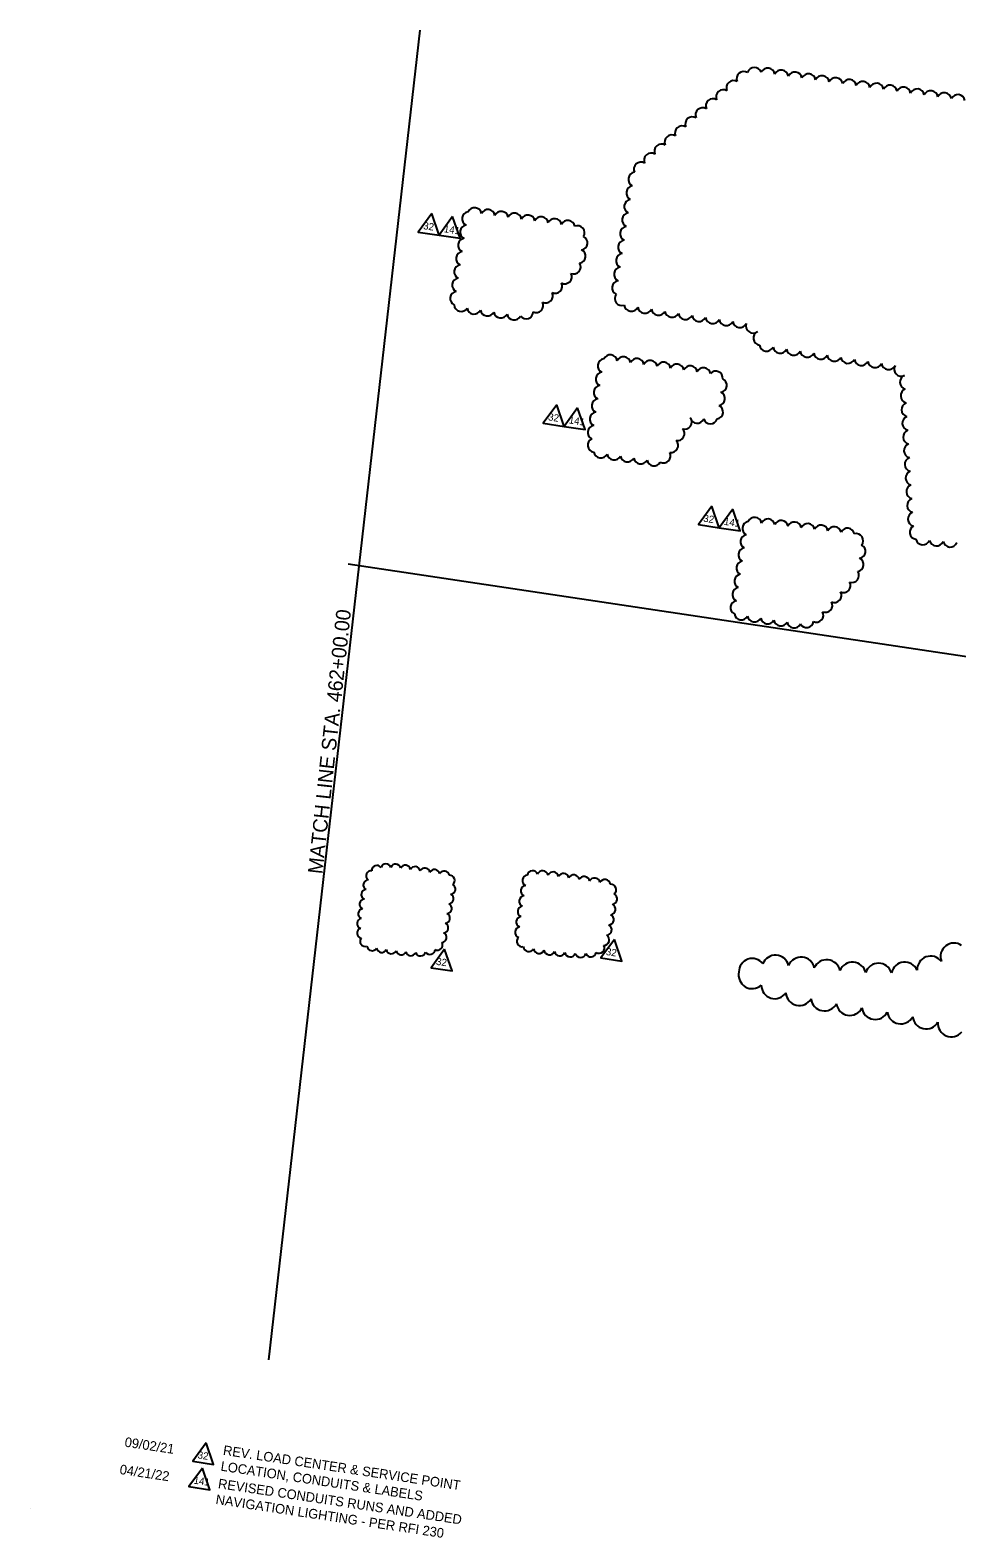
# Model space of a CAD drawing. Extents: x 924436 to 925782, y 636346 to 637319.
# Drawn here: x 924436 to 924943, y 636495 to 637319 of the extents above; entities that cross this region are included whole.
import ezdxf

# ---------------------------------------------------------------- set-up
doc = ezdxf.new("R2010")
doc.units = 0
for name, color, linetype in [('ActivePointCell_dp', 7, 'Continuous'), ('AdhocPoint_dp', 7, 'Continuous'), ('Cloud_dp', 7, 'Continuous'), ('MatchLines_dp', 7, 'Continuous'), ('TextLabel', 7, 'Continuous'), ('TextNotes', 7, 'Continuous')]:
    doc.layers.add(name, color=color, linetype=linetype)

msp = doc.modelspace()

# ---------------------------------------------------------------- linework, layer by layer
at = {"layer": 'ActivePointCell_dp'}
msp.add_line((924609.88, 637027.58), (925702.36, 636864), dxfattribs=at)
at = {"layer": 'AdhocPoint_dp'}
msp.add_line((924435.98, 636511.22), (924435.98, 636511.22), dxfattribs=at)
at = {"layer": 'Cloud_dp'}
for points in [[(924655.53, 637219.18), (924648.17, 637209.03), (924659.6, 637207.32)], [(924666.96, 637217.47), (924659.6, 637207.32), (924671.02, 637205.61)], [(924723.84, 637114.64), (924716.48, 637104.49), (924727.91, 637102.78)], [(924735.27, 637112.93), (924727.91, 637102.78), (924739.33, 637101.07)], [(924808.68, 637059.19), (924801.32, 637049.04), (924812.75, 637047.33)], [(924820.11, 637057.48), (924812.75, 637047.33), (924824.17, 637045.62)], [(924755.42, 636822.21), (924748.06, 636812.07), (924759.49, 636810.36)], [(924662.57, 636816.88), (924655.21, 636806.73), (924666.63, 636805.02)]]:
    msp.add_lwpolyline(points, close=True, dxfattribs=at)
for centre, radius, start, end in [((924826.13, 637292.91), 3.93, 58.88945, 203.88945), ((924831.93, 637295.16), 3.93, 18.56609, 163.56609), ((924839.2, 637294.72), 3.93, 9.6019, 154.6019), ((924846.63, 637293.69), 3.93, 9.6019, 154.6019), ((924854.06, 637292.66), 3.93, 9.6019, 154.6019), ((924861.48, 637291.63), 3.93, 9.6019, 154.6019), ((924820.51, 637287.95), 3.93, 58.88945, 203.88945), ((924868.91, 637290.6), 3.93, 9.6019, 154.6019), ((924876.33, 637289.57), 3.93, 9.6019, 154.6019), ((924883.76, 637288.54), 3.93, 9.6019, 154.6019), ((924891.18, 637287.51), 3.93, 9.6019, 154.6019), ((924898.61, 637286.48), 3.93, 9.6019, 154.6019), ((924906.03, 637285.45), 3.93, 9.6019, 154.6019), ((924913.46, 637284.42), 3.93, 9.6019, 154.6019), ((924920.88, 637283.39), 3.93, 9.6019, 154.6019), ((924809.26, 637278.04), 3.93, 58.88945, 203.88945), ((924814.88, 637282.99), 3.93, 58.88945, 203.88945), ((924928.31, 637282.36), 3.93, 9.6019, 154.6019), ((924935.73, 637281.33), 3.93, 9.6019, 154.6019), ((924943.16, 637280.28), 3.94, 9.27297, 154.27297), ((924798.01, 637268.12), 3.93, 58.88945, 203.88945), ((924803.63, 637273.08), 3.93, 58.88945, 203.88945), ((924792.39, 637263.17), 3.93, 58.88945, 203.88945), ((924781.14, 637253.25), 3.93, 58.88945, 203.88945), ((924786.76, 637258.21), 3.93, 58.88945, 203.88945), ((924769.89, 637243.34), 3.93, 58.88945, 203.88945), ((924775.51, 637248.3), 3.93, 58.88945, 203.88945), ((924766.91, 637237.87), 3.93, 98.98411, 243.98411), ((924765.8, 637230.45), 3.93, 98.98411, 243.98411), ((924678.9, 637218.52), 3.86, 9.69938, 154.69938), ((924686.19, 637217.52), 3.86, 9.69938, 154.69938), ((924764.69, 637223.04), 3.93, 98.98411, 243.98411), ((924674.93, 637209.08), 3.86, 98.98411, 243.98411), ((924676.02, 637216.36), 3.86, 98.98411, 243.98411), ((924693.47, 637216.52), 3.86, 9.69938, 154.69938), ((924700.76, 637215.52), 3.86, 9.69938, 154.69938), ((924708.05, 637214.52), 3.86, 9.69938, 154.69938), ((924715.33, 637213.52), 3.86, 9.69938, 154.69938), ((924722.62, 637212.53), 3.86, 9.69938, 154.69938), ((924729.9, 637211.53), 3.86, 9.69938, 154.69938), ((924763.58, 637215.63), 3.93, 98.98411, 243.98411), ((924673.84, 637201.81), 3.86, 98.98411, 243.98411), ((924735.21, 637208.63), 3.86, 328.02413, 113.02413), ((924736.81, 637203.11), 3.86, 279.30403, 64.30403), ((924761.36, 637200.8), 3.93, 98.98411, 243.98411), ((924762.47, 637208.21), 3.93, 98.98411, 243.98411), ((924672.75, 637194.54), 3.86, 98.98411, 243.98411), ((924735.76, 637195.83), 3.86, 279.30403, 64.30403), ((924760.25, 637193.39), 3.93, 98.98411, 243.98411), ((924671.66, 637187.26), 3.86, 98.98411, 243.98411), ((924733.13, 637189.98), 3.86, 247.21121, 32.21121), ((924759.14, 637185.97), 3.93, 98.98411, 243.98411), ((924670.57, 637179.99), 3.86, 98.98411, 243.98411), ((924723.05, 637179.39), 3.86, 242.81513, 27.81513), ((924728.22, 637184.62), 3.86, 242.81513, 27.81513), ((924758.03, 637178.56), 3.93, 98.98411, 243.98411), ((924669.48, 637172.72), 3.86, 98.98411, 243.98411), ((924717.88, 637174.16), 3.86, 242.81513, 27.81513), ((924759.49, 637172.72), 3.93, 144.02662, 289.02662), ((924671.64, 637169.46), 3.85, 183.16682, 328.16682), ((924678.72, 637168.03), 3.86, 188.98411, 333.98411), ((924685.99, 637166.95), 3.86, 188.98411, 333.98411), ((924693.27, 637165.86), 3.86, 188.98411, 333.98411), ((924700.54, 637164.77), 3.86, 188.98411, 333.98411), ((924707.09, 637165.38), 3.85, 216.78941, 1.78941), ((924712.71, 637168.93), 3.86, 242.81513, 27.81513), ((924764.65, 637169.62), 3.93, 188.98411, 333.98411), ((924772.06, 637168.51), 3.93, 188.98411, 333.98411), ((924779.48, 637167.4), 3.93, 188.98411, 333.98411), ((924786.89, 637166.29), 3.93, 188.98411, 333.98411), ((924794.3, 637165.18), 3.93, 188.98411, 333.98411), ((924801.72, 637164.07), 3.93, 188.98411, 333.98411), ((924809.13, 637162.96), 3.93, 188.98411, 333.98411), ((924816.55, 637161.85), 3.93, 188.98411, 333.98411), ((924823.96, 637160.74), 3.93, 188.98411, 333.98411), ((924831.21, 637157.75), 3.93, 161.22808, 306.22808), ((924835.28, 637151.1), 3.89, 116.6552, 261.6552), ((924838.59, 637147.86), 3.93, 188.89284, 333.89284), ((924750.17, 637135.85), 3.86, 98.98411, 243.98411), ((924753.05, 637138.01), 3.86, 9.68197, 154.68197), ((924760.34, 637137.01), 3.86, 9.68197, 154.68197), ((924767.64, 637136.01), 3.86, 9.68197, 154.68197), ((924774.93, 637135.01), 3.86, 9.68197, 154.68197), ((924846.01, 637146.74), 3.93, 188.89284, 333.89284), ((924853.42, 637145.62), 3.93, 188.89284, 333.89284), ((924860.83, 637144.49), 3.93, 188.89284, 333.89284), ((924868.24, 637143.37), 3.93, 188.89284, 333.89284), ((924875.65, 637142.25), 3.93, 188.89284, 333.89284), ((924883.06, 637141.13), 3.93, 188.89284, 333.89284), ((924890.48, 637140.01), 3.93, 188.89284, 333.89284), ((924749.08, 637128.57), 3.86, 98.98411, 243.98411), ((924782.22, 637134.01), 3.86, 9.68197, 154.68197), ((924789.51, 637133), 3.86, 9.68197, 154.68197), ((924796.8, 637132), 3.86, 9.68197, 154.68197), ((924804.09, 637131), 3.86, 9.68197, 154.68197), ((924810.8, 637129.12), 3.86, 353.97234, 138.97234), ((924897.89, 637138.88), 3.93, 188.89284, 333.89284), ((924905.31, 637137.76), 3.94, 188.89284, 333.89284), ((924912.27, 637134.12), 3.92, 150.88593, 295.88593), ((924915.38, 637126.93), 3.93, 110.89209, 255.89209), ((924747.99, 637121.29), 3.86, 98.98411, 243.98411), ((924812.98, 637125.23), 3.86, 279.5168, 64.5168), ((924915.82, 637119.44), 3.93, 110.89209, 255.89209), ((924746.9, 637114.02), 3.86, 98.98411, 243.98411), ((924810.94, 637110.66), 3.86, 279.5168, 64.5168), ((924811.96, 637117.94), 3.86, 279.5168, 64.5168), ((924916.27, 637111.96), 3.93, 110.89209, 255.89209), ((924745.81, 637106.74), 3.86, 98.98411, 243.98411), ((924793.79, 637105.16), 3.86, 251.64788, 36.64788), ((924800.65, 637108.31), 3.86, 192.74467, 337.74467), ((924807.9, 637108.01), 3.86, 197.49791, 342.49791), ((924916.71, 637104.48), 3.93, 110.89209, 255.89209), ((924744.72, 637099.46), 3.86, 98.98411, 243.98411), ((924789.83, 637098.79), 3.86, 259.51444, 44.51444), ((924917.15, 637096.99), 3.93, 110.89209, 255.89209), ((924744.72, 637092.52), 3.86, 115.97008, 260.97008), ((924786.38, 637092.29), 3.86, 259.51444, 44.51444), ((924917.6, 637089.51), 3.93, 110.89209, 255.89209), ((924747.92, 637089.32), 3.86, 188.98411, 333.98411), ((924755.2, 637088.23), 3.86, 188.98411, 333.98411), ((924762.48, 637087.14), 3.86, 188.98411, 333.98411), ((924769.76, 637086.05), 3.86, 188.98411, 333.98411), ((924777.03, 637084.96), 3.86, 188.98411, 333.98411), ((924782.26, 637086.7), 3.86, 242.8424, 27.8424), ((924918.04, 637082.03), 3.93, 110.89209, 255.89209), ((924918.49, 637074.54), 3.93, 110.89209, 255.89209), ((924918.93, 637067.06), 3.93, 110.89209, 255.89209), ((924919.37, 637059.58), 3.93, 110.89209, 255.89209), ((924829.14, 637046.98), 3.83, 98.98411, 243.98411), ((924832.03, 637049.2), 3.83, 10.84278, 155.84278), ((924839.28, 637048.35), 3.83, 10.84278, 155.84278), ((924846.54, 637047.5), 3.83, 10.84278, 155.84278), ((924853.79, 637046.66), 3.83, 10.84278, 155.84278), ((924861.05, 637045.81), 3.83, 10.84278, 155.84278), ((924868.3, 637044.96), 3.83, 10.84278, 155.84278), ((924875.55, 637044.12), 3.83, 10.84278, 155.84278), ((924919.82, 637052.09), 3.94, 110.89209, 255.89209), ((924920.66, 637044.87), 3.85, 117.95353, 262.95353), ((924828.05, 637039.76), 3.83, 98.98411, 243.98411), ((924882.81, 637043.27), 3.83, 10.84278, 155.84278), ((924887.56, 637040.29), 3.83, 320.05109, 105.05109), ((924924.02, 637041.92), 3.93, 192.80022, 337.80022), ((924931.49, 637041.31), 3.93, 192.80022, 337.80022), ((924938.97, 637040.69), 3.93, 192.80022, 337.80022), ((924826.97, 637032.54), 3.83, 98.98411, 243.98411), ((924888.84, 637034.39), 3.83, 279.29199, 64.29199), ((924825.89, 637025.31), 3.83, 98.98411, 243.98411), ((924885.27, 637021.19), 3.83, 249.85694, 34.85694), ((924887.79, 637027.16), 3.83, 279.29199, 64.29199), ((924824.81, 637018.09), 3.83, 98.98411, 243.98411), ((924880.64, 637015.68), 3.83, 245.07106, 30.07106), ((924822.65, 637003.65), 3.83, 98.98411, 243.98411), ((924823.73, 637010.87), 3.83, 98.98411, 243.98411), ((924870.78, 637004.9), 3.83, 245.07106, 30.07106), ((924875.71, 637010.29), 3.83, 245.07106, 30.07106), ((924824.75, 637000.76), 3.83, 188.30813, 333.30813), ((924831.95, 636999.64), 3.83, 188.98411, 333.98411), ((924865.86, 636999.51), 3.83, 245.07106, 30.07106), ((924839.18, 636998.56), 3.83, 188.98411, 333.98411), ((924846.4, 636997.47), 3.83, 188.98411, 333.98411), ((924853.62, 636996.39), 3.83, 188.98411, 333.98411), ((924860.44, 636996.51), 3.83, 207.92147, 352.92147), ((924622.48, 636856.98), 2.82, 85.72902, 230.72902), ((924625.52, 636859.86), 2.82, 36.48479, 181.48479), ((924630.49, 636860.73), 2.82, 18.22494, 163.22494), ((924635.78, 636860.54), 2.82, 12.74786, 157.74786), ((924641.09, 636859.97), 2.82, 9.88809, 154.88809), ((924646.4, 636859.21), 2.82, 8.98411, 153.98411), ((924651.72, 636858.42), 2.82, 8.98411, 153.98411), ((924657.05, 636857.62), 2.82, 8.98411, 153.98411), ((924662.37, 636856.82), 2.82, 8.98411, 153.98411), ((924710.6, 636856.75), 3.01, 22.10621, 167.10621), ((924716.16, 636856.72), 3.01, 12.25515, 157.25515), ((924721.83, 636856.1), 3.01, 10.2339, 155.2339), ((924727.51, 636855.32), 3.01, 9.21064, 154.21064), ((924620.92, 636851.98), 2.82, 94.43828, 239.43828), ((924665.28, 636854.44), 2.82, 307.56851, 92.56851), ((924665.67, 636849.72), 2.82, 276.72488, 61.72488), ((924707.21, 636848.79), 3.01, 98.98411, 243.98411), ((924708.09, 636854.44), 3.01, 98.21119, 243.21119), ((924733.18, 636854.48), 3.01, 8.98411, 153.98411), ((924738.86, 636853.63), 3.01, 8.98411, 153.98411), ((924744.53, 636852.78), 3.01, 8.98411, 153.98411), ((924750.21, 636851.93), 3.01, 8.98411, 153.98411), ((924753.39, 636849.4), 3.01, 308.91031, 93.91031), ((924618.9, 636841.47), 2.82, 98.30208, 243.30208), ((924619.82, 636846.75), 2.82, 96.94529, 241.94529), ((924664.66, 636844.43), 2.82, 276.75589, 61.75589), ((924706.36, 636843.11), 3.01, 98.98411, 243.98411), ((924753.92, 636844.37), 3.01, 278.18047, 63.18047), ((924617.56, 636830.87), 2.82, 103.36672, 248.36672), ((924618.11, 636836.17), 2.82, 99.77206, 244.77206), ((924662.71, 636833.84), 2.82, 277.48651, 62.48651), ((924663.67, 636839.14), 2.82, 277.05268, 62.05268), ((924704.72, 636831.76), 3.01, 100.03156, 245.03156), ((924705.51, 636837.44), 3.01, 99.13208, 244.13208), ((924752.03, 636833.06), 3.01, 277.48854, 62.48854), ((924752.99, 636838.71), 3.01, 278.18042, 63.18042), ((924617.54, 636825.61), 2.82, 111.02904, 256.02904), ((924660.84, 636823.25), 2.82, 276.32619, 61.32619), ((924661.8, 636828.52), 2.82, 278.0572, 63.0572), ((924704.08, 636826.09), 3.01, 102.07512, 247.07512), ((924750.94, 636827.46), 3.01, 275.51216, 60.51216), ((924619.15, 636821.23), 2.82, 144.49935, 289.49935), ((924622.9, 636818.85), 2.82, 185.67258, 330.67258), ((924628.15, 636817.92), 2.82, 189.13804, 334.13804), ((924658.64, 636819.16), 2.82, 242.14498, 27.14498), ((924705.05, 636821.21), 3.01, 135.41295, 280.41295), ((924708.59, 636818.55), 3.01, 185.69771, 330.69771), ((924746.92, 636817.61), 3.01, 241.45375, 26.45375), ((924749.55, 636821.96), 3.01, 271.18929, 56.18929), ((924941.06, 636812.82), 7.39, 55.59614, 200.59614), ((924633.46, 636817.2), 2.82, 190.5172, 335.5172), ((924638.8, 636816.59), 2.82, 191.31649, 336.31649), ((924644.12, 636816.11), 2.82, 193.37372, 338.37372), ((924649.4, 636816.02), 2.82, 199.77202, 344.77202), ((924654.51, 636816.79), 2.82, 212.43843, 357.43843), ((924714.19, 636817.56), 3.01, 189.24654, 334.24654), ((924719.85, 636816.81), 3.01, 190.6975, 335.6975), ((924725.54, 636816.18), 3.01, 191.67782, 336.67782), ((924731.23, 636815.68), 3.01, 193.31541, 338.31541), ((924736.92, 636815.41), 3.01, 196.16364, 341.16364), ((924742.54, 636815.61), 3.01, 202.83651, 347.83651), ((924830.71, 636804.56), 7.22, 36.10691, 181.10691), ((924843.46, 636806.19), 7.4, 14.26643, 159.26643), ((924857.44, 636805.13), 7.4, 12.01739, 157.01739), ((924871.45, 636803.69), 7.4, 11.27554, 156.27554), ((924885.57, 636802.4), 7.39, 13.31169, 158.31169), ((924899.79, 636801.8), 7.39, 16.85486, 161.85486), ((924914.1, 636802.42), 7.39, 23.07976, 168.07976), ((924928.29, 636805.68), 7.4, 37.82703, 182.82703), ((924830.74, 636802.72), 7.45, 166.81553, 311.81553), ((924843.11, 636797.2), 7.4, 180.25625, 325.25625), ((924856.57, 636793.48), 7.39, 183.90206, 328.90206), ((924870.25, 636790.5), 7.39, 186.46428, 331.46428), ((924884.07, 636788.05), 7.4, 188.42741, 333.42741), ((924898, 636785.81), 7.39, 188.32278, 333.32278), ((924911.94, 636783.41), 7.39, 187.15665, 332.15665), ((924925.84, 636780.65), 7.39, 185.33698, 330.33698), ((924939.63, 636776.35), 7.39, 175.05812, 320.05812)]:
    msp.add_arc(centre, radius, start, end, dxfattribs=at)
at = {"layer": 'MatchLines_dp'}
msp.add_line((924648.99, 637319.45), (924566.29, 636592.31), dxfattribs=at)
at = {"layer": 'TextNotes'}
for points in [[(924532.24, 636546.98), (924524.87, 636536.83), (924536.3, 636535.12)], [(924530.16, 636533.14), (924522.8, 636522.99), (924534.23, 636521.28)]]:
    msp.add_lwpolyline(points, close=True, dxfattribs=at)

# ---------------------------------------------------------------- texts
at = {"layer": 'Cloud_dp'}
for s, p in [('32', (924650.66, 637210.66)), ('141', (924661.96, 637208.97)), ('32', (924718.97, 637106.12)), ('141', (924730.28, 637104.43)), ('32', (924803.81, 637050.67)), ('141', (924815.11, 637048.98)), ('32', (924750.54, 636813.7)), ('32', (924657.69, 636808.36))]:
    msp.add_text(s, height=3.938, rotation=351.48411, dxfattribs=at).set_placement(p)
at = {"layer": 'MatchLines_dp'}
msp.add_text('MATCH LINE STA. 462+00.00', height=8, rotation=83.78998, dxfattribs=at).set_placement((924595.72, 636857.71))
at = {"layer": 'TextLabel'}
for s, p in [('09/02/21', (924487.37, 636544.88)), ('REV. LOAD CENTER & SERVICE POINT ', (924541.18, 636540.4)), ('LOCATION, CONDUITS & LABELS', (924539.88, 636531.74)), ('04/21/22', (924484.65, 636529.93)), ('REVISED CONDUITS RUNS AND ADDED ', (924538.45, 636522.17)), ('NAVIGATION LIGHTING - PER RFI 230', (924537.15, 636513.52))]:
    msp.add_text(s, height=5.25, rotation=351.48411, dxfattribs=at).set_placement(p)
at = {"layer": 'TextNotes'}
for s, p in [('32', (924527.36, 636538.46)), ('141', (924525.17, 636524.64))]:
    msp.add_text(s, height=3.938, rotation=351.48411, dxfattribs=at).set_placement(p)

doc.saveas('drawing.dxf')
